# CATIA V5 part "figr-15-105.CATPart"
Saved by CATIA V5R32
Part number: Part1
Bounding box of the stored display mesh (mm): x -66.07 to 66.07, y -35.456 to 35.456, z -8 to 1
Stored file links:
  D:\PROJECTS\Project 2022\CATIA V5 6R 2022\Resources\Part Files\c15_catia_v5_6r2022_prt\figr-15-105.CATPart
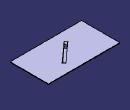
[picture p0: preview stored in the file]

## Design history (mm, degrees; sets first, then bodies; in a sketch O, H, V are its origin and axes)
SheetMetalParameters1: Thickness 1, BendRadius 5, KFactor 0.5 {= log(min(100,max(20*SheetMetalParameters1.BendRadius,SheetMetalParameters1.Thickness)/SheetMetalParameters1.Thickness))/log(100)/2}, ReliefRadialLength 1, ReliefAxialLength 2, MinimumBendRadius 0
Body1 (main body)
  Sketch1 on xy-plane, origin (0, 0, 0), H (1, 0, 0), V (0, 1, 0)
    line L1 (66.07, 35.4565) -> (66.07, -35.4565)
    line L2 (66.07, -35.4565) -> (-66.07, -35.4565)
    line L3 (-66.07, -35.4565) -> (-66.07, 35.4565)
    line L4 (-66.07, 35.4565) -> (66.07, 35.4565)
    vertical: L1 V, L3 V
    horizontal: L2 H, L4 H
    equidistance: L1 L3 O, L2 L4 O
  Wall1: Thickness 1, Profile Sketch1
  Sketch2 on face of Wall1, origin (0, 0, 1), H (1, 0, 0), V (0, 1, 0)
    point P1 (0, 0)
    coincidence: P1 O
  Sketch3 on face of Wall1, origin (0, 0, 1), H (1, 0, 0), V (0, 1, 0)
    point P1 (0, 0)
    reference projected point E1 (0, 0) from Sketch2.P1
    coincidence: E1 P1
  d_Stamp1: Stamp_FilletRadius 2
